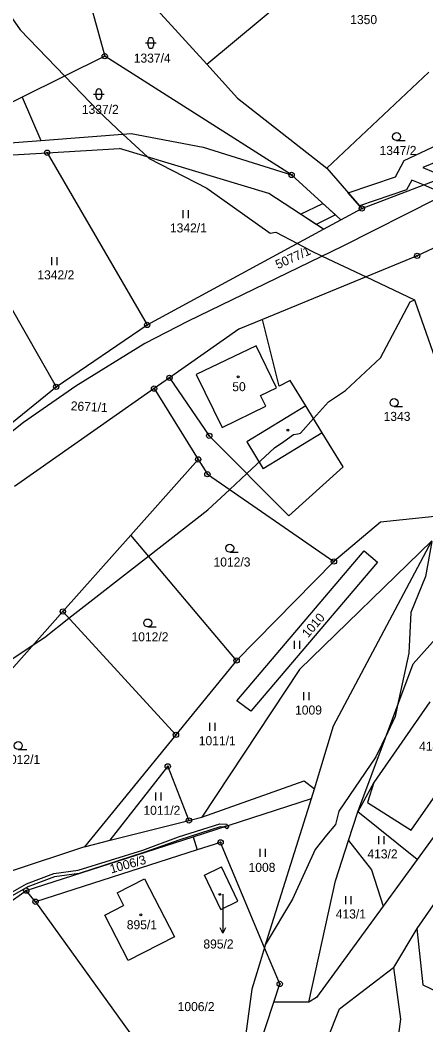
# Model space of a CAD drawing. Extents: x -439246 to -433691, y -1130252 to -1121148.
# Drawn here: x -437823.2 to -437746.8, y -1124136.2 to -1123946.9 of the extents above; entities that cross this region are included whole.
import ezdxf

# ---------------------------------------------------------------- set-up
doc = ezdxf.new("R2010")
doc.units = 0
for name, color, linetype in [('Vrstva 1', 7, 'Continuous'), ('Vrstva 16', 7, 'Continuous'), ('Vrstva 18', 7, 'Continuous'), ('Vrstva 19', 7, 'Continuous'), ('Vrstva 24', 7, 'Continuous'), ('Vrstva 25', 7, 'Continuous'), ('Vrstva 3', 7, 'Continuous'), ('Vrstva 30', 7, 'Continuous'), ('Vrstva 37', 7, 'Continuous'), ('Vrstva 4', 7, 'Continuous'), ('Vrstva 52', 7, 'Continuous')]:
    doc.layers.add(name, color=color, linetype=linetype)

msp = doc.modelspace()

# ---------------------------------------------------------------- linework, layer by layer
at = {"layer": 'Vrstva 1'}
for points in [[(-437804.71, -1123936.86), (-437788, -1123955.23)], [(-437811.43, -1123938.42), (-437807.26, -1123953.71)], [(-437788, -1123955.23), (-437772.42, -1123942.14)], [(-437807.26, -1123953.71), (-437822.82, -1123961.42)], [(-437772.05, -1123976.08), (-437807.26, -1123953.71)], [(-437788, -1123955.23), (-437782.22, -1123961.59)], [(-437765.45, -1123974.78), (-437746.2, -1123956.71)], [(-437822.82, -1123961.42), (-437828.67, -1123964.32)], [(-437822.82, -1123961.42), (-437819.27, -1123969.56)], [(-437782.22, -1123961.59), (-437765.45, -1123974.78)], [(-437819.27, -1123969.56), (-437802.29, -1123968.25)], [(-437802.29, -1123968.25), (-437788.74, -1123970.83)], [(-437837.59, -1123970.97), (-437819.27, -1123969.56)], [(-437840.83, -1123973.26), (-437818.09, -1123971.9)], [(-437818.09, -1123971.9), (-437804.48, -1123971.08)], [(-437818.09, -1123971.9), (-437799.27, -1124004.34)], [(-437776.32, -1123979.6), (-437804.48, -1123971.08)], [(-437788.74, -1123970.83), (-437772.05, -1123976.08)], [(-437727.13, -1123971.68), (-437762.43, -1123989.47)], [(-437772.05, -1123976.08), (-437762.76, -1123984.53)], [(-437765.45, -1123974.78), (-437758.83, -1123982.4)], [(-437758.83, -1123982.4), (-437739.77, -1123975.1)], [(-437766.06, -1123986.32), (-437776.32, -1123979.6)], [(-437762.76, -1123984.53), (-437758.83, -1123982.4)], [(-437766.06, -1123986.32), (-437762.76, -1123984.53)], [(-437799.27, -1124004.34), (-437766.06, -1123986.32)], [(-437743.6, -1123989.04), (-437748.4, -1123991.32)], [(-437831.1, -1123990.3), (-437816.41, -1124016)], [(-437762.43, -1123989.47), (-437791.66, -1124003.71)], [(-437748.4, -1123991.32), (-437777.52, -1124003.3)], [(-437816.41, -1124016), (-437799.27, -1124004.34)], [(-437791.66, -1124003.71), (-437799.67, -1124007.86)], [(-437777.52, -1124003.3), (-437781.97, -1124005.13)], [(-437774.37, -1124015.88), (-437777.52, -1124003.3)], [(-437781.97, -1124005.13), (-437795.05, -1124014.3)], [(-437799.67, -1124007.86), (-437812.67, -1124015.9)], [(-437812.67, -1124015.9), (-437822.57, -1124022.74)], [(-437795.05, -1124014.3), (-437797.96, -1124016.34)], [(-437795.05, -1124014.3), (-437787.57, -1124025.22)], [(-437772.32, -1124014.79), (-437774.37, -1124015.88)], [(-437769.39, -1124019.59), (-437772.32, -1124014.79)], [(-437848.87, -1124042.29), (-437816.41, -1124016)], [(-437797.96, -1124016.34), (-437824.28, -1124034.78)], [(-437797.96, -1124016.34), (-437789.65, -1124029.67)], [(-437766.28, -1124024.69), (-437769.39, -1124019.59)], [(-437822.57, -1124022.74), (-437839.06, -1124035.8)], [(-437787.57, -1124025.22), (-437772.55, -1124040.32)], [(-437762.36, -1124031.1), (-437766.28, -1124024.69)], [(-437802.36, -1124043.96), (-437789.65, -1124029.67)], [(-437789.65, -1124029.67), (-437787.91, -1124032.46)], [(-437787.91, -1124032.46), (-437764.08, -1124048.9)], [(-437772.55, -1124040.32), (-437762.36, -1124031.1)], [(-437743.88, -1124040.31), (-437755.3, -1124041.5)], [(-437755.3, -1124041.5), (-437764.08, -1124048.9)], [(-437815.15, -1124058.33), (-437802.36, -1124043.96)], [(-437782.42, -1124067.55), (-437802.36, -1124043.96)], [(-437749.15, -1124068.21), (-437727.15, -1124043.5)], [(-437745.62, -1124045.03), (-437770.58, -1124069.24)], [(-437764.15, -1124079.88), (-437745.62, -1124045.03)], [(-437782.35, -1124075.13), (-437758.4, -1124046.92)], [(-437758.4, -1124046.92), (-437755.9, -1124049.05)], [(-437764.08, -1124048.9), (-437782.42, -1124067.55)], [(-437755.9, -1124049.05), (-437779.72, -1124077.11)], [(-437837.58, -1124083.54), (-437815.15, -1124058.33)], [(-437793.85, -1124081.56), (-437815.15, -1124058.33)], [(-437782.42, -1124067.55), (-437793.85, -1124081.56)], [(-437759.57, -1124096.05), (-437749.15, -1124068.21)], [(-437770.58, -1124069.24), (-437788.97, -1124097.08)], [(-437779.72, -1124077.11), (-437782.35, -1124075.13)], [(-437746.02, -1124075.33), (-437756.54, -1124090.52)], [(-437767.75, -1124091.73), (-437764.15, -1124079.88)], [(-437749.55, -1124099.53), (-437735.84, -1124079.93)], [(-437793.85, -1124081.56), (-437811.05, -1124102.64)], [(-437731.21, -1124081.39), (-437748.42, -1124105.02)], [(-437726.03, -1124085.79), (-437748.46, -1124118.07)], [(-437806.21, -1124101.42), (-437795.38, -1124087.51)], [(-437795.38, -1124087.51), (-437791.39, -1124097.69)], [(-437788.97, -1124097.08), (-437769.66, -1124090.25)], [(-437769.66, -1124090.25), (-437767.75, -1124091.73)], [(-437756.54, -1124090.52), (-437759.57, -1124096.05)], [(-437756.54, -1124090.52), (-437757.78, -1124094.29)], [(-437768.33, -1124093.57), (-437767.75, -1124091.73)], [(-437790.62, -1124100.76), (-437768.33, -1124093.57)], [(-437777.14, -1124121.67), (-437768.33, -1124093.57)], [(-437757.78, -1124094.29), (-437749.55, -1124099.53)], [(-437791.39, -1124097.69), (-437788.97, -1124097.08)], [(-437761.31, -1124101.47), (-437759.57, -1124096.05)], [(-437748.42, -1124105.02), (-437759.57, -1124096.05)], [(-437806.21, -1124101.42), (-437791.39, -1124097.69)], [(-437822.03, -1124110.9), (-437790.62, -1124100.76)], [(-437790.62, -1124100.76), (-437789.82, -1124103.23)], [(-437811.05, -1124102.64), (-437824.87, -1124107.27)], [(-437811.05, -1124102.64), (-437806.21, -1124101.42)], [(-437785.43, -1124101.82), (-437789.82, -1124103.23)], [(-437777.14, -1124121.67), (-437785.43, -1124101.82)], [(-437763.76, -1124109.09), (-437761.31, -1124101.47)], [(-437761.31, -1124101.47), (-437756.98, -1124106.97)], [(-437789.82, -1124103.23), (-437820.3, -1124113)], [(-437788.49, -1124108.02), (-437785.25, -1124106.46)], [(-437782.16, -1124112.89), (-437785.25, -1124106.46)], [(-437748.42, -1124105.02), (-437754.82, -1124113.81)], [(-437804.91, -1124111.33), (-437799.75, -1124108.67)], [(-437799.75, -1124108.67), (-437794.12, -1124119.61)], [(-437785.4, -1124114.45), (-437788.49, -1124108.02)], [(-437756.98, -1124106.97), (-437754.82, -1124113.81)], [(-437768.84, -1124131.93), (-437763.76, -1124109.09)], [(-437825.76, -1124113.54), (-437822.03, -1124110.9)], [(-437820.3, -1124113), (-437822.03, -1124110.9)], [(-437804.91, -1124111.33), (-437803.69, -1124113.69)], [(-437820.3, -1124113), (-437793.46, -1124150.26)], [(-437807.25, -1124115.52), (-437803.69, -1124113.69)], [(-437785.4, -1124114.45), (-437782.16, -1124112.89)], [(-437754.82, -1124113.81), (-437767.38, -1124131.06)], [(-437802.83, -1124124.09), (-437807.25, -1124115.52)], [(-437748.46, -1124118.07), (-437752.89, -1124125.37)], [(-437748.46, -1124118.07), (-437747.32, -1124128.69)], [(-437794.12, -1124119.61), (-437802.83, -1124124.09)], [(-437774.29, -1124128.5), (-437777.14, -1124121.67)], [(-437763.04, -1124133.16), (-437752.89, -1124125.37)], [(-437752.89, -1124125.37), (-437751.54, -1124135.16)], [(-437775.41, -1124131.93), (-437774.29, -1124128.5)], [(-437747.32, -1124128.69), (-437738.8, -1124132.76)], [(-437767.38, -1124131.06), (-437768.84, -1124131.93)], [(-437783.19, -1124155.59), (-437775.41, -1124131.93)], [(-437768.84, -1124131.93), (-437775.41, -1124131.93)], [(-437774.28, -1124161.46), (-437763.04, -1124133.16)], [(-437751.54, -1124135.16), (-437752.86, -1124144.97)]]:
    msp.add_lwpolyline(points, dxfattribs=at)
at = {"layer": 'Vrstva 16'}
msp.add_line((-437785, -1124115.91), (-437785, -1124118.91), dxfattribs=at)
for points in [[(-437785, -1124111.61), (-437785, -1124115.91)], [(-437784.5, -1124117.91), (-437785, -1124118.91), (-437785.5, -1124117.91)]]:
    msp.add_lwpolyline(points, dxfattribs=at)
at = {"layer": 'Vrstva 24'}
for centre, radius in [((-437807.26, -1123953.71), 0.5), ((-437807.26, -1123953.71), 0.1), ((-437818.09, -1123971.9), 0.5), ((-437818.09, -1123971.9), 0.1), ((-437772.05, -1123976.08), 0.5), ((-437772.05, -1123976.08), 0.1), ((-437758.83, -1123982.4), 0.5), ((-437758.83, -1123982.4), 0.1), ((-437748.4, -1123991.32), 0.5), ((-437748.4, -1123991.32), 0.1), ((-437799.27, -1124004.34), 0.5), ((-437799.27, -1124004.34), 0.1), ((-437795.05, -1124014.3), 0.5), ((-437816.41, -1124016), 0.5), ((-437816.41, -1124016), 0.1), ((-437797.96, -1124016.34), 0.5), ((-437795.05, -1124014.3), 0.1), ((-437797.96, -1124016.34), 0.1), ((-437787.57, -1124025.22), 0.5), ((-437787.57, -1124025.22), 0.1), ((-437789.65, -1124029.67), 0.5), ((-437789.65, -1124029.67), 0.1), ((-437787.91, -1124032.46), 0.5), ((-437787.91, -1124032.46), 0.1), ((-437764.08, -1124048.9), 0.5), ((-437764.08, -1124048.9), 0.1), ((-437815.15, -1124058.33), 0.5), ((-437815.15, -1124058.33), 0.1), ((-437782.42, -1124067.55), 0.5), ((-437782.42, -1124067.55), 0.1), ((-437793.85, -1124081.56), 0.5), ((-437793.85, -1124081.56), 0.1), ((-437795.38, -1124087.51), 0.5), ((-437795.38, -1124087.51), 0.1), ((-437791.39, -1124097.69), 0.5), ((-437791.39, -1124097.69), 0.1), ((-437785.43, -1124101.82), 0.5), ((-437785.43, -1124101.82), 0.1), ((-437822.03, -1124110.9), 0.5), ((-437822.03, -1124110.9), 0.1), ((-437820.3, -1124113), 0.5), ((-437820.3, -1124113), 0.1), ((-437774.29, -1124128.5), 0.5), ((-437774.29, -1124128.5), 0.1)]:
    msp.add_circle(centre, radius, dxfattribs=at)
at = {"layer": 'Vrstva 25'}
for p, q in [((-437799.57, -1123951.22), (-437797.57, -1123951.22)), ((-437799.07, -1123951.72), (-437799.07, -1123950.72)), ((-437798.07, -1123950.72), (-437798.07, -1123951.72)), ((-437809.36, -1123960.87), (-437807.36, -1123960.87)), ((-437808.86, -1123961.37), (-437808.86, -1123960.37)), ((-437807.86, -1123960.37), (-437807.86, -1123961.37)), ((-437752.27, -1123969.61), (-437750.67, -1123969.61)), ((-437792.48, -1123984.21), (-437792.48, -1123982.71)), ((-437791.48, -1123984.21), (-437791.48, -1123982.71)), ((-437817.23, -1123993.05), (-437817.23, -1123991.55)), ((-437816.23, -1123993.05), (-437816.23, -1123991.55)), ((-437752.75, -1124019.72), (-437751.15, -1124019.72)), ((-437783.71, -1124047.15), (-437782.11, -1124047.15)), ((-437799.15, -1124061.24), (-437797.55, -1124061.24)), ((-437771.49, -1124065.35), (-437771.49, -1124063.85)), ((-437770.49, -1124065.35), (-437770.49, -1124063.85)), ((-437769.77, -1124075.04), (-437769.77, -1124073.54)), ((-437768.77, -1124075.04), (-437768.77, -1124073.54)), ((-437787.43, -1124080.82), (-437787.43, -1124079.32)), ((-437786.43, -1124080.82), (-437786.43, -1124079.32)), ((-437823.54, -1124084.34), (-437821.94, -1124084.34)), ((-437797.64, -1124093.93), (-437797.64, -1124092.43)), ((-437796.64, -1124093.93), (-437796.64, -1124092.43)), ((-437755.65, -1124102.15), (-437755.65, -1124100.65)), ((-437754.65, -1124102.15), (-437754.65, -1124100.65)), ((-437777.97, -1124104.54), (-437777.97, -1124103.04)), ((-437776.97, -1124104.54), (-437776.97, -1124103.04)), ((-437761.83, -1124113.46), (-437761.83, -1124111.96)), ((-437760.83, -1124113.46), (-437760.83, -1124111.96))]:
    msp.add_line(p, q, dxfattribs=at)
for centre, radius in [((-437752.27, -1123968.86), 0.75), ((-437782.13, -1124014.12), 0.175), ((-437752.75, -1124018.97), 0.75), ((-437772.74, -1124024.17), 0.175), ((-437783.71, -1124046.4), 0.75), ((-437799.15, -1124060.49), 0.75), ((-437823.54, -1124083.59), 0.75), ((-437785.56, -1124111.62), 0.175), ((-437800.45, -1124115.49), 0.175)]:
    msp.add_circle(centre, radius, dxfattribs=at)
for centre, start, end in [((-437798.57, -1123950.72), 0, 180), ((-437798.57, -1123951.72), 180, 0), ((-437808.36, -1123960.37), 0, 180), ((-437808.36, -1123961.37), 180, 0)]:
    msp.add_arc(centre, 0.5, start, end, dxfattribs=at)
at = {"layer": 'Vrstva 3'}
for points in [[(-437778.76, -1124008.25), (-437790.02, -1124013.69)], [(-437774.89, -1124016.16), (-437778.76, -1124008.25)], [(-437790.02, -1124013.69), (-437785.12, -1124023.68)], [(-437777.9, -1124017.63), (-437774.89, -1124016.16)], [(-437776.91, -1124019.65), (-437777.9, -1124017.63)], [(-437785.12, -1124023.68), (-437776.91, -1124019.65)], [(-437788.49, -1124108.02), (-437785.25, -1124106.46)], [(-437782.16, -1124112.89), (-437785.25, -1124106.46)], [(-437804.91, -1124111.33), (-437799.75, -1124108.67)], [(-437799.75, -1124108.67), (-437794.12, -1124119.61)], [(-437785.4, -1124114.45), (-437788.49, -1124108.02)], [(-437804.91, -1124111.33), (-437803.69, -1124113.69)], [(-437807.25, -1124115.52), (-437803.69, -1124113.69)], [(-437785.4, -1124114.45), (-437782.16, -1124112.89)], [(-437802.83, -1124124.09), (-437807.25, -1124115.52)], [(-437794.12, -1124119.61), (-437802.83, -1124124.09)]]:
    msp.add_lwpolyline(points, dxfattribs=at)
at = {"layer": 'Vrstva 30'}
for points in [[(-437749.39, -1123977.05), (-437750.39, -1123978.91), (-437759.28, -1123981.89), (-437761.4, -1123979.44), (-437752.47, -1123976.45), (-437750.83, -1123973.38), (-437742.46, -1123969.4), (-437741.16, -1123972.15), (-437747.31, -1123974.67), (-437743.19, -1123976.41), (-437739.77, -1123975.1), (-437728.8, -1123969.53), (-437719.39, -1123964.65), (-437714.62, -1123963.12), (-437710.03, -1123963.77), (-437715.02, -1123966.08), (-437717.31, -1123965.76), (-437727.13, -1123971.68), (-437737.8, -1123977.06), (-437744.05, -1123979.3), (-437747.23, -1123977.96), (-437749.39, -1123977.05)], [(-437770.38, -1123983.49), (-437766.16, -1123981.44), (-437763.78, -1123983.61), (-437767.46, -1123985.4), (-437770.38, -1123983.49)], [(-437816.86, -1124107.71), (-437812.23, -1124107.05), (-437800.09, -1124103.28), (-437793.33, -1124100.77), (-437785.56, -1124098.31), (-437784.32, -1124098.42), (-437784.08, -1124098.65), (-437785.03, -1124098.96), (-437785.5, -1124098.91), (-437793.13, -1124101.33), (-437799.92, -1124103.76), (-437812.07, -1124107.69), (-437816.72, -1124108.29), (-437821.75, -1124110.17), (-437824.7, -1124111.9)], [(-437783.86, -1124098.85), (-437784.28, -1124099.29), (-437784.58, -1124099), (-437785.03, -1124098.96), (-437784.08, -1124098.65), (-437783.86, -1124098.85)], [(-437822.01, -1124109.63), (-437816.86, -1124107.71)], [(-437825.08, -1124111.42), (-437822.01, -1124109.63)]]:
    msp.add_lwpolyline(points, dxfattribs=at)
at = {"layer": 'Vrstva 37'}
for centre in [(-437782.13, -1124014.12), (-437785.56, -1124111.62), (-437800.45, -1124115.49)]:
    msp.add_circle(centre, 0.175, dxfattribs=at)
at = {"layer": 'Vrstva 4'}
for points in [[(-437778.76, -1124008.25), (-437790.02, -1124013.69)], [(-437774.89, -1124016.16), (-437778.76, -1124008.25)], [(-437790.02, -1124013.69), (-437785.12, -1124023.68)], [(-437777.9, -1124017.63), (-437774.89, -1124016.16)], [(-437776.91, -1124019.65), (-437777.9, -1124017.63)], [(-437785.12, -1124023.68), (-437776.91, -1124019.65)], [(-437769.39, -1124019.59), (-437780.5, -1124026.38)], [(-437766.28, -1124024.69), (-437777.39, -1124031.47)], [(-437780.5, -1124026.38), (-437777.39, -1124031.47)]]:
    msp.add_lwpolyline(points, dxfattribs=at)
at = {"layer": 'Vrstva 52'}
for points in [[(-437829.76, -1123939.33), (-437823.16, -1123948.71), (-437814.79, -1123957.44), (-437808.45, -1123964.05), (-437803.83, -1123968.37), (-437799.2, -1123972.69), (-437798.86, -1123973), (-437788, -1123978.54), (-437776.07, -1123987.06), (-437775, -1123986.85), (-437770.97, -1123988.98), (-437768.34, -1123990.37), (-437766.28, -1123991.35), (-437758.01, -1123995.27), (-437748.92, -1123999.59)], [(-437771.67, -1124024.97), (-437770.9, -1124024.84), (-437770.4, -1124024.75), (-437767.93, -1124021.98), (-437765.09, -1124018.8), (-437761.9, -1124016.68), (-437755.32, -1124010.52), (-437749.71, -1124000), (-437748.92, -1123999.59)], [(-437748.92, -1123999.59), (-437748.78, -1124000), (-437743.42, -1124015.19)], [(-437826.28, -1124068.31), (-437820.75, -1124064.62), (-437818.63, -1124063.21), (-437813.99, -1124059.59), (-437799.01, -1124047.92), (-437787.82, -1124039.2), (-437783.7, -1124035.36), (-437780.48, -1124032.35), (-437775.29, -1124027.51), (-437773.53, -1124026.28), (-437771.67, -1124024.97)], [(-437745.67, -1124045.13), (-437746.82, -1124051.74), (-437749.58, -1124058.54), (-437750, -1124066.18), (-437752.16, -1124076.26), (-437752.55, -1124078.08), (-437753.96, -1124081.06), (-437756.16, -1124085.73), (-437763.18, -1124095.93), (-437763.81, -1124098.48), (-437765.46, -1124100.49), (-437767.64, -1124103.15), (-437771.89, -1124112.5), (-437776.87, -1124120.8), (-437776.99, -1124121), (-437777.17, -1124121.6), (-437777.92, -1124124.12), (-437779.53, -1124129.5), (-437781.64, -1124144.85)]]:
    msp.add_lwpolyline(points, dxfattribs=at)

# ---------------------------------------------------------------- texts
at = {"layer": 'Vrstva 16'}
for s, rotation, p in [('5077/1', 24.4644, (-437774.63, -1123993.84)), ('2671/1', 356.9708, (-437813.69, -1124020.41))]:
    msp.add_text(s, height=1.7, rotation=rotation, dxfattribs=at).set_placement(p)
msp.add_text('895/2', height=1.7, dxfattribs=at).set_placement((-437788.67, -1124121.82))
at = {"layer": 'Vrstva 18'}
for s, p in [('1350', (-437761.01, -1123947.66)), ('1337/4', (-437801.79, -1123954.92)), ('1337/2', (-437811.57, -1123964.57)), ('1347/2', (-437755.49, -1123972.31)), ('1342/1', (-437794.97, -1123986.91)), ('1342/2', (-437819.94, -1123995.75)), ('1343', (-437754.73, -1124022.42)), ('1012/3', (-437786.76, -1124049.85)), ('1012/2', (-437802.21, -1124063.94)), ('1009', (-437771.4, -1124077.74)), ('1011/1', (-437789.54, -1124083.52)), ('414/1', (-437748.04, -1124084.57)), ('1012/1', (-437826.37, -1124087.04)), ('1011/2', (-437799.97, -1124096.63)), ('413/2', (-437757.78, -1124104.85)), ('1008', (-437780.16, -1124107.38)), ('413/1', (-437763.74, -1124116.16)), ('1006/2', (-437793.52, -1124133.61))]:
    msp.add_text(s, height=1.7, dxfattribs=at).set_placement(p)
for s, rotation, p in [('1010', 49.2963, (-437768.97, -1124063.39)), ('1006/3', 15.7073, (-437806.02, -1124107.69))]:
    msp.add_text(s, height=1.7, rotation=rotation, dxfattribs=at).set_placement(p)
at = {"layer": 'Vrstva 19'}
for s, height, p in [('50', 1.7, (-437783.23, -1124016.82)), ('895/2', 0.1, (-437785.19, -1124111.62)), ('895/1', 1.7, (-437803.1, -1124118.19))]:
    msp.add_text(s, height=height, dxfattribs=at).set_placement(p)

doc.saveas('drawing.dxf')
